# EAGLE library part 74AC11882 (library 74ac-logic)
COMPARATOR
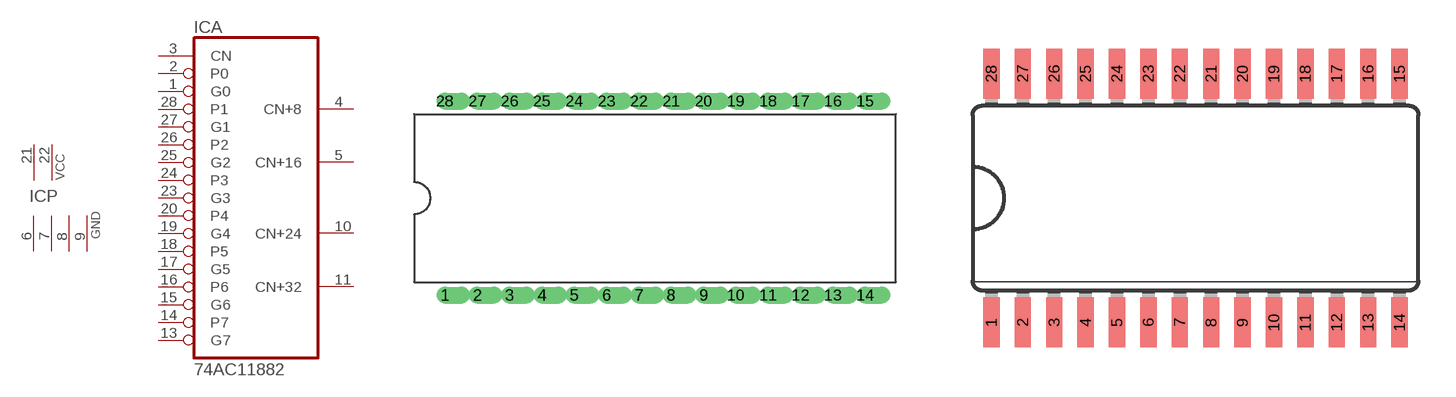
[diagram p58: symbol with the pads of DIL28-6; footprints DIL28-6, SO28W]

Designator prefix IC; gates A=7411882 P=2PWR4GND

## 74AC11882  [DIL28-6]
1  A:G0  in
2  A:P0  in
3  A:CN  in
4  A:CN+8  out
5  A:CN+16  out
6  P:GND  pwr
7  P:GND  pwr
8  P:GND  pwr
9  P:GND  pwr
10  A:CN+24  out
11  A:CN+32  out
13  A:G7  in
14  A:P7  in
15  A:G6  in
16  A:P6  in
17  A:G5  in
18  A:P5  in
19  A:G4  in
20  A:P4  in
21  P:VCC  pwr
22  P:VCC  pwr
23  A:G3  in
24  A:P3  in
25  A:G2  in
26  A:P2  in
27  A:G1  in
28  A:P1  in

## 74AC11882D  [SO28W]
Pads as for DIL28-6

## Footprint DIL28-6 (pad centres in mm)
Dual In Line 0.6 inch
drill 0.813 offset: 1 -16.51,-7.62; 2 -13.97,-7.62; 3 -11.43,-7.62; 4 -8.89,-7.62; 5 -6.35,-7.62; 6 -3.81,-7.62; 7 -1.27,-7.62; 8 1.27,-7.62; 9 3.81,-7.62; 10 6.35,-7.62; 11 8.89,-7.62; 12 11.43,-7.62; 13 13.97,-7.62; 14 16.51,-7.62; 15 16.51,7.62; 16 13.97,7.62; 17 11.43,7.62; 18 8.89,7.62; 19 6.35,7.62; 20 3.81,7.62; 21 1.27,7.62; 22 -1.27,7.62; 23 -3.81,7.62; 24 -6.35,7.62; 25 -8.89,7.62; 26 -11.43,7.62; 27 -13.97,7.62; 28 -16.51,7.62

## Footprint SO28W (pad centres in mm)
Wide Small Outline package 300 mil
smd 0.66 x 2.032: 1 -8.255,-5.029; 2 -6.985,-5.029; 3 -5.715,-5.029; 4 -4.445,-5.029; 5 -3.175,-5.029; 6 -1.905,-5.029; 7 -0.635,-5.029; 8 0.635,-5.029; 9 1.905,-5.029; 10 3.175,-5.029; 11 4.445,-5.029; 12 5.715,-5.029; 13 6.985,-5.029; 14 8.255,-5.029; 15 8.255,5.029; 16 6.985,5.029; 17 5.715,5.029; 18 4.445,5.029; 19 3.175,5.029; 20 1.905,5.029; 21 0.635,5.029; 22 -0.635,5.029; 23 -1.905,5.029; 24 -3.175,5.029; 25 -4.445,5.029; 26 -5.715,5.029; 27 -6.985,5.029; 28 -8.255,5.029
